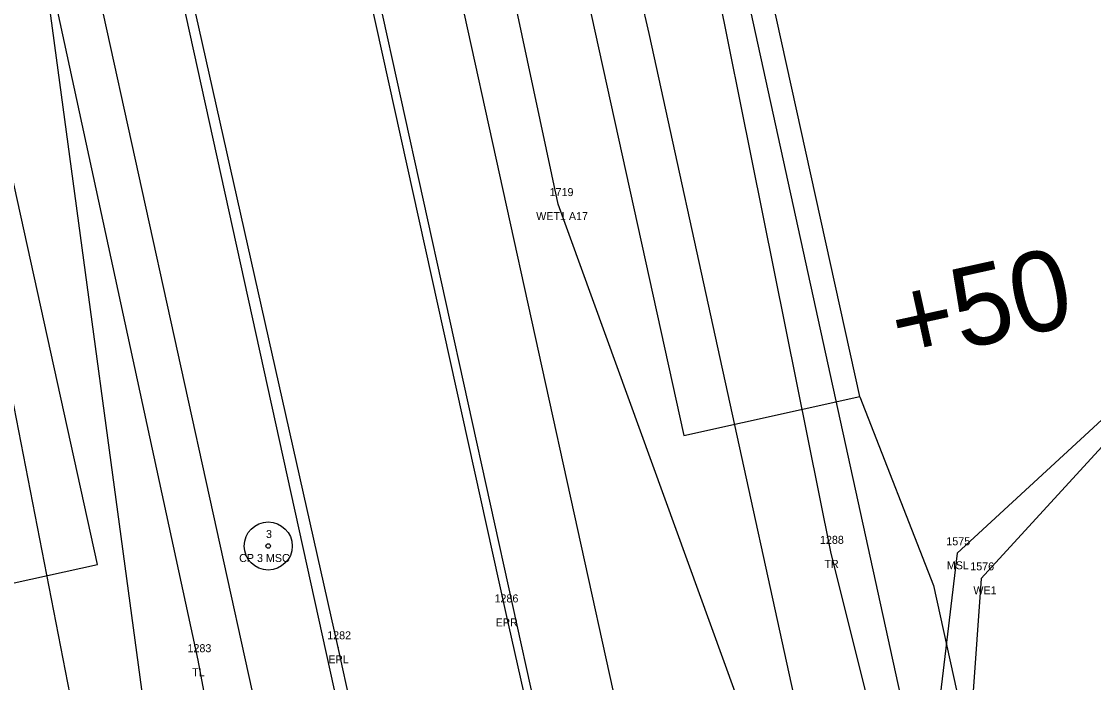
# Model space of a CAD drawing. Extents: x 2521558 to 2525396, y 882711 to 887632.
# Drawn here: x 2523710.8 to 2523844.7, y 885245.8 to 885328.4 of the extents above; entities that cross this region are included whole.
import ezdxf

# ---------------------------------------------------------------- set-up
doc = ezdxf.new("R2010")
doc.units = 0
for name, color, linetype in [('RD_EV_JurisArea', 7, 'Continuous'), ('RD_EX_H2O', 7, 'Continuous'), ('RD_EX_H2O_txCode', 7, 'Continuous'), ('RD_EX_H2O_WetLd_txCode', 7, 'Continuous'), ('RD_EX_Misc', 7, 'Continuous'), ('RD_EX_Misc_txCode', 7, 'Continuous'), ('RD_EX_Road', 7, 'Continuous'), ('RD_EX_Road_txCode', 7, 'Continuous'), ('RD_EX_RW_TX', 7, 'Continuous'), ('RD_EX_VEG', 7, 'Continuous'), ('RD_EX_VEG_txCode', 7, 'Continuous'), ('RD_HC_Data', 7, 'Continuous'), ('RD_HC_txCode', 7, 'Continuous'), ('RD_PD_BCA', 7, 'Continuous'), ('RD_PD_CstnLmt', 7, 'Continuous'), ('RD_PD_DR_ErosCtrl', 7, 'Continuous'), ('RD_PD_Final_TrvlWay', 7, 'Continuous'), ('RD_PD_GR', 7, 'Continuous'), ('RD_Sketch9', 7, 'Continuous'), ('RD_SMD_Locator', 7, 'Continuous')]:
    doc.layers.add(name, color=color, linetype=linetype)

msp = doc.modelspace()

# ---------------------------------------------------------------- linework, layer by layer
at = {"layer": 'RD_EV_JurisArea'}
for points in [[(2523761.17, 885134.03), (2523740.58, 885149.03), (2523730.55, 885209.77), (2523710.6, 885357.47), (2523698.09, 885411.19), (2523674.93, 885498.62), (2523657.6, 885564.24), (2523640.82, 885610.87), (2523583.66, 885726.91), (2523539.21, 885693.17), (2523494.42, 885646.98)], [(2523761.17, 885134.03), (2523808.21, 885149.21), (2523821.91, 885178.64), (2523802.85, 885236.55), (2523777.81, 885305.56), (2523748.2, 885444.32), (2523730.68, 885516.88), (2523708.64, 885617.3), (2523698.71, 885662.02), (2523727.83, 885665.82), (2523757.3, 885671.75)]]:
    msp.add_lwpolyline(points, dxfattribs=at)
at = {"layer": 'RD_EX_H2O'}
msp.add_lwpolyline([(2524064.86, 885165.15), (2524036.37, 885213.78), (2524057.22, 885252.72), (2524031.95, 885291.63), (2523983.25, 885326.3), (2523940.61, 885311.83), (2523904.84, 885305.01), (2523874.98, 885272.1), (2523850.32, 885280.24), (2523830.66, 885258.8), (2523826.93, 885206.61)], dxfattribs=at)
at = {"layer": 'RD_EX_Misc'}
msp.add_lwpolyline([(2524066.31, 885165.35), (2524037.3, 885214.15), (2524057.95, 885253.07), (2524039.52, 885283.17), (2524032.92, 885292.57), (2523983.53, 885327.98), (2523940.24, 885313.27), (2523904.13, 885306.25), (2523874.86, 885272.67), (2523849.96, 885282.51), (2523827.65, 885261.93), (2523821.38, 885209.28)], dxfattribs=at)
at = {"layer": 'RD_EX_Road'}
for p, q in [((2523771.24, 885254.79), (2523751.35, 885344.92)), ((2523750.32, 885250.18), (2523730.02, 885340.63)), ((2523792.78, 885159.31), (2523771.24, 885254.79)), ((2523771.58, 885154.56), (2523750.32, 885250.18))]:
    msp.add_line(p, q, dxfattribs=at)
at = {"layer": 'RD_EX_VEG'}
for points in [[(2523825.62, 885207.01), (2523811.87, 885262.11), (2523733.02, 885654.22), (2523687.11, 885876.24)], [(2523749.81, 885158.06), (2523732.86, 885248.57), (2523691.62, 885438.95), (2523639.52, 885601.04)]]:
    msp.add_lwpolyline(points, dxfattribs=at)
at = {"layer": 'RD_HC_Data'}
for radius in [3, 0.282]:
    msp.add_circle((2523741.6, 885262.84), radius, dxfattribs=at)
at = {"layer": 'RD_PD_BCA'}
for p, q in [((2523815.5, 885281.49), (2523824.71, 885257.89)), ((2523824.7, 885257.92), (2523830.05, 885233.47))]:
    msp.add_line(p, q, dxfattribs=at)
at = {"layer": 'RD_PD_CstnLmt'}
for p, q in [((2523766.59, 885424.32), (2523789.14, 885326.89)), ((2523789.14, 885326.89), (2523810.51, 885229.2)), ((2523704.35, 885308.21), (2523723.51, 885210.04))]:
    msp.add_line(p, q, dxfattribs=at)
at = {"layer": 'RD_PD_DR_ErosCtrl'}
msp.add_line((2523801.84, 885329.66), (2523823.21, 885231.97), dxfattribs=at)
at = {"layer": 'RD_PD_Final_TrvlWay'}
for p, q in [((2523720.24, 885490.91), (2524037.44, 884050.42)), ((2523696.8, 885485.75), (2524014, 884045.26))]:
    msp.add_line(p, q, dxfattribs=at)
at = {"layer": 'RD_PD_GR'}
for p, q in [((2523742.1, 885438.13), (2523790.49, 885218.39)), ((2523747.52, 885208.93), (2523699.13, 885428.66))]:
    msp.add_line(p, q, dxfattribs=at)
at = {"layer": 'RD_Sketch9'}
for p, q in [((2523815.5, 885281.5), (2523767.12, 885501.23)), ((2523745.14, 885496.39), (2523793.53, 885276.66)), ((2523720.28, 885260.53), (2523671.9, 885480.26)), ((2523793.53, 885276.66), (2523815.5, 885281.5)), ((2523698.31, 885255.69), (2523720.28, 885260.53))]:
    msp.add_line(p, q, dxfattribs=at)
at = {"layer": 'RD_SMD_Locator'}
for centre in [(2523777.81, 885305.56), (2523741.6, 885262.84), (2523811.87, 885262.11), (2523827.65, 885261.93), (2523830.66, 885258.8), (2523771.24, 885254.79), (2523750.32, 885250.18), (2523732.86, 885248.57)]:
    msp.add_circle(centre, 0.001, dxfattribs=at)

# ---------------------------------------------------------------- texts
at = {"layer": 'RD_EX_H2O_txCode'}
for s, p in [('1576', (2523829.29, 885259.8)), ('WE1', (2523829.68, 885256.8))]:
    msp.add_text(s, height=1, dxfattribs=at).set_placement(p)
at = {"layer": 'RD_EX_H2O_WetLd_txCode'}
for s, p in [('1719', (2523776.75, 885306.56)), ('WET1 A17', (2523775.07, 885303.56))]:
    msp.add_text(s, height=1, dxfattribs=at).set_placement(p)
at = {"layer": 'RD_EX_Misc_txCode'}
for s, p in [('1575', (2523826.3, 885262.93)), ('MSL', (2523826.36, 885259.93))]:
    msp.add_text(s, height=1, dxfattribs=at).set_placement(p)
at = {"layer": 'RD_EX_Road_txCode'}
for s, p in [('1286', (2523769.87, 885255.79)), ('EPR', (2523770.01, 885252.79)), ('1282', (2523748.97, 885251.18)), ('EPL', (2523749.11, 885248.18))]:
    msp.add_text(s, height=1, dxfattribs=at).set_placement(p)
at = {"layer": 'RD_EX_RW_TX'}
msp.add_text('+50', height=10, rotation=12.4185, dxfattribs=at).set_placement((2523820.51, 885285.69))
at = {"layer": 'RD_EX_VEG_txCode'}
for s, p in [('1288', (2523810.52, 885263.11)), ('TR', (2523811.07, 885260.11)), ('1283', (2523731.52, 885249.57)), ('TL', (2523732.09, 885246.57))]:
    msp.add_text(s, height=1, dxfattribs=at).set_placement(p)
at = {"layer": 'RD_HC_Data'}
msp.add_text('N 39%%d 17\' 08" E', height=6, rotation=50.7144, dxfattribs=at).set_placement((2523841.2, 885210.9))
at = {"layer": 'RD_HC_txCode'}
for s, p in [('3', (2523741.32, 885263.84)), ('CP 3 MSC', (2523737.97, 885260.84))]:
    msp.add_text(s, height=1, dxfattribs=at).set_placement(p)

doc.saveas('drawing.dxf')
